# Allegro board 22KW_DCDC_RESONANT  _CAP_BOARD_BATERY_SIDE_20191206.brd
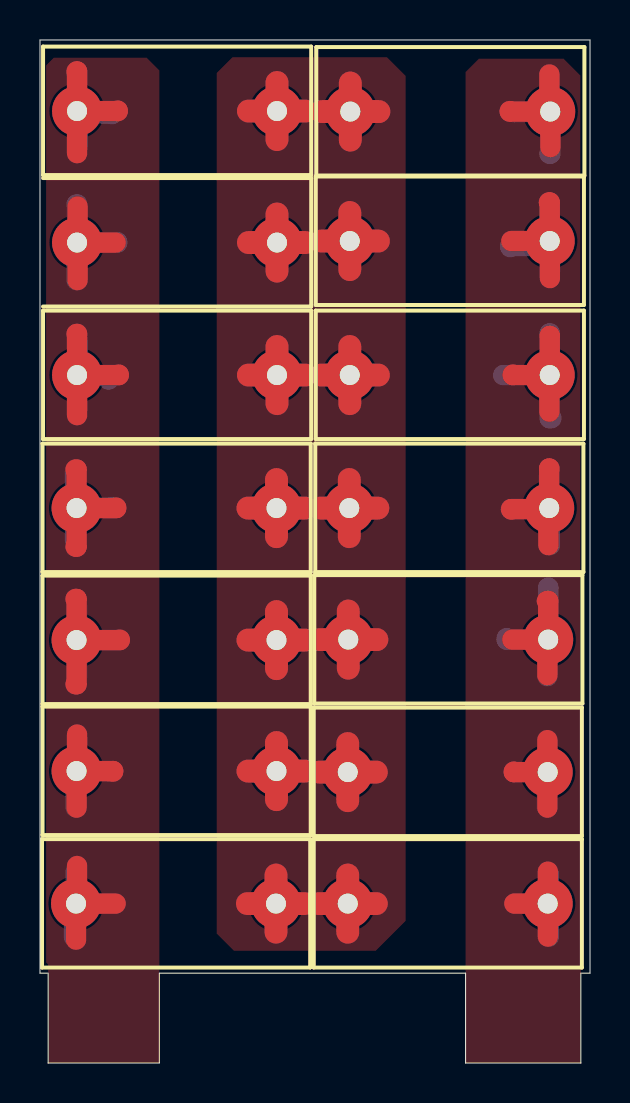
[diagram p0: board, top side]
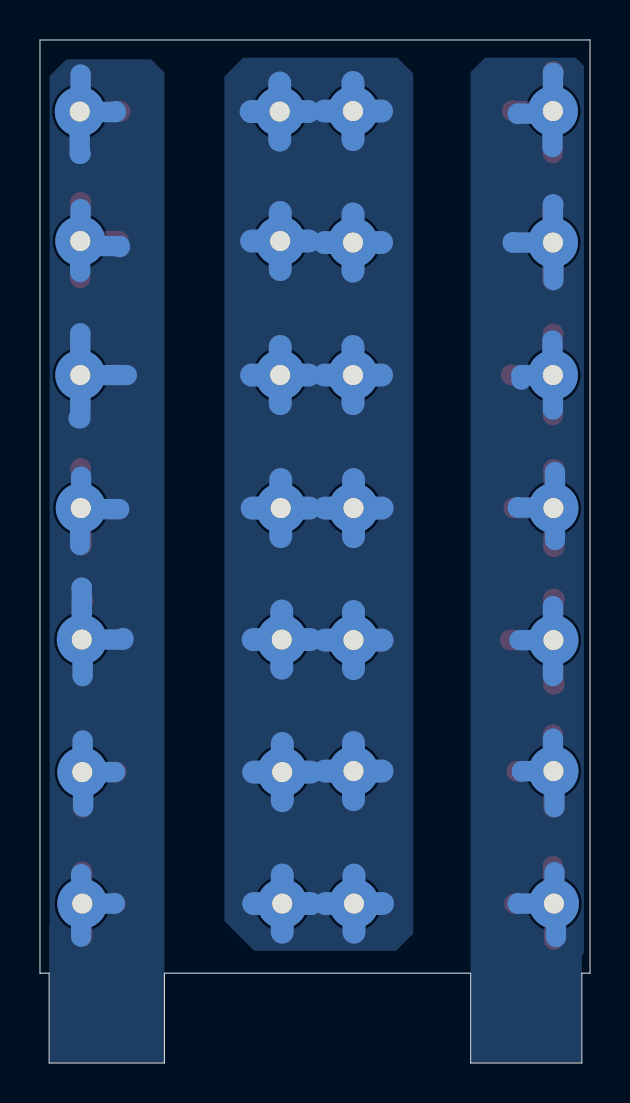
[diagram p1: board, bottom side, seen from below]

Outline 27.51 x 51.18 mm; copper layers: TOP, BOTTOM. Coordinates in mm from the lower left corner of the outline.
Outline path: 0,51.18 27.51,51.18 27.51,4.5 27.05,4.5 27.05,0 21.29,0 21.29,4.5 5.97,4.5 5.97,0 0.41,0 0.41,4.5 0,4.5 0,51.18

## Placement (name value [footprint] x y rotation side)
C1  6.8n  [B32651A7682J000]  1.83 27.76 0 top
C2  6.8n  [B32651A7682J000]  1.8 7.98 0 top
C3  6.8n  [B32651A7682J000]  1.83 14.61 0 top
C4  6.8n  [B32651A7682J000]  1.85 34.42 0 top
C6  6.8n  [B32651A7682J000]  1.85 41.05 0 top
C7  6.8n  [B32651A7682J000]  1.83 21.16 0 top
C9  6.8n  [B32651A7682J000]  1.85 47.62 0 top
C11  6.8n  [B32651A7682J000]  15.47 27.76 0 top
C12  6.8n  [B32651A7682J000]  15.39 7.98 0 top
C13  6.8n  [B32651A7682J000]  15.39 14.55 0 top
C14  6.8n  [B32651A7682J000]  15.49 34.42 0 top
C16  6.8n  [B32651A7682J000]  15.49 41.12 0 top
C17  6.8n  [B32651A7682J000]  15.42 21.18 0 top
C19  6.8n  [B32651A7682J000]  15.52 47.6 0 top

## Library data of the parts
C1-C4 C6 C7 C9 C11-C14 C16 C17 C19 = CAP NP

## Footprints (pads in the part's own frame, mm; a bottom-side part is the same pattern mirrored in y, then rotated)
B32651A7682J000
  round 2.5 hole 1: 1(0,0) 2(10,0)

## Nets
N00441: C1.1 C2.1 C3.1 C4.1 C6.1 C7.1 C9.1
N03629: C1.2 C2.2 C3.2 C4.2 C6.2 C7.2 C9.2 C11.1 C12.1 C13.1 C14.1 C16.1 C17.1 C19.1
N03669: C11.2 C12.2 C13.2 C14.2 C16.2 C17.2 C19.2

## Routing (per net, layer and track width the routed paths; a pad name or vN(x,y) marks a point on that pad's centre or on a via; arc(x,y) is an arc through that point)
N00441: length 78.9
  TOP w1.016: C4.1 1.85,32.41 ; C4.1 1.85,36.47 1.83,36.47 ; C4.1 3.94,34.42 3.94,34.44 ; 1.78,29.69 1.83,29.69 C1.1 ; 1.88,41.05 3.78,41.05 ; 1.88,41.05 1.88,39.17 ; 1.88,41.05 1.88,42.85 ; 1.88,41.05 C6.1 ; 1.78,25.83 1.83,25.83 C1.1 ; C1.1 3.81,27.76 3.81,27.79 ; C9.1 1.85,49.61 1.83,49.61 ; C9.1 3.89,47.62 3.89,47.65 ; C9.1 1.85,45.52 ; 1.85,14.61 C3.1 1.83,12.78 ; 1.85,14.61 3.66,14.61 3.66,14.58 ; 1.85,14.61 1.85,16.43 ; 1.8,6.17 C2.1 1.85,7.98 ; C7.1 3.99,21.16 3.99,21.18 ; C7.1 1.83,23.22 1.78,23.22 ; C7.1 1.83,18.95 1.78,18.95 ; 1.85,9.86 1.85,7.98 ; 1.85,7.98 3.78,7.98
  BOTTOM w1.016: C6.1 1.83,41.05 1.83,39.17 ; C6.1 1.85,42.95 1.83,42.95 ; C6.1 3.86,41.05 3.86,41.07 ; 1.85,32.69 C4.1 1.88,34.42 ; 1.78,7.98 1.7,7.98 1.7,6.3 ; 1.78,7.98 C2.1 3.61,7.98 3.61,8 ; 1.78,7.98 1.78,9.55 ; 1.88,45.82 1.88,47.5 3.61,47.5 3.61,47.47 ; 1.85,16.23 1.85,14.61 ; 1.85,14.61 C3.1 1.78,14.61 1.78,12.8 ; 1.85,14.61 3.4,14.61 3.4,14.58 ; 1.85,21.16 3.53,21.16 ; 1.85,21.16 1.85,22.86 ; 1.85,21.16 1.85,19.35 ; 1.85,21.16 C7.1 ; 3.43,34.19 3.43,34.42 1.88,34.42 ; 1.88,36.14 1.88,34.42 ; 1.75,27.79 1.75,26.16 ; 1.75,27.79 1.75,29.57 ; 1.75,27.79 3.61,27.79 3.61,27.81 ; C9.1 1.85,49.53 1.83,49.53
N03629: length 160.1
  TOP w1.143: C16.1 15.49,42.55 ; C16.1 16.92,41.12 ; C16.1 14.06,41.12 ; C16.1 15.49,39.69 ; 15.47,26.33 C11.1 ; C11.1 14.04,27.76 ; C11.1 16.9,27.76 ; C11.1 15.47,29.19 ; 10.4,27.76 C1.2 ; C1.2 11.83,26.33 ; C1.2 13.26,27.76 ; C1.2 11.83,29.19 ; 11.85,32.99 C4.2 ; C4.2 11.85,35.85 ; C4.2 10.42,34.42 ; C4.2 13.28,34.42 ; 11.85,39.62 C6.2 ; C6.2 11.85,42.48 ; C6.2 10.42,41.05 ; C6.2 13.28,41.05 ; C14.1 15.49,35.85 ; C14.1 16.92,34.42 ; C14.1 14.06,34.42 ; C14.1 15.49,32.99 ; 13.99,21.18 C17.1 ; C17.1 16.85,21.18 ; C17.1 15.42,19.75 ; C17.1 15.42,22.61 ; 15.39,6.55 C12.1 ; C12.1 13.96,7.98 ; C12.1 16.82,7.98 ; C12.1 15.39,9.41 ; 11.85,46.2 C9.2 ; C9.2 11.85,49.05 ; C9.2 13.28,47.62 ; C9.2 10.42,47.62 ; 11.8,6.55 C2.2 ; C2.2 13.23,7.98 ; C2.2 10.37,7.98 ; C2.2 11.8,9.41 ; 10.4,14.61 C3.2 ; C3.2 11.83,13.18 ; C3.2 13.26,14.61 ; C3.2 11.83,16.03 ; 15.39,13.12 C13.1 ; C13.1 13.96,14.55 ; C13.1 16.82,14.55 ; C13.1 15.39,15.98 ; 15.52,46.17 C19.1 ; C19.1 14.09,47.6 ; C19.1 16.95,47.6 ; C19.1 15.52,49.03 ; C7.2 11.83,22.59 ; C7.2 11.83,19.73 ; C7.2 13.26,21.16 ; C7.2 10.4,21.16
  BOTTOM w1.143: C16.1 16.92,41.12 ; C16.1 15.49,39.69 ; C16.1 14.06,41.12 ; C16.1 15.49,42.55 ; C9.2 13.28,47.62 ; C9.2 11.85,46.2 ; C9.2 10.42,47.62 ; C9.2 11.85,49.05 ; 10.4,27.76 C1.2 ; C1.2 13.26,27.76 ; C1.2 11.83,29.19 ; C1.2 11.83,26.33 ; C12.1 15.39,9.41 ; C12.1 16.82,7.98 ; C12.1 15.39,6.55 ; C12.1 13.96,7.98 ; C2.2 11.8,9.41 ; C2.2 13.23,7.98 ; C2.2 11.8,6.55 ; C2.2 10.37,7.98 ; 15.47,26.33 C11.1 ; C11.1 16.9,27.76 ; C11.1 15.47,29.19 ; C11.1 14.04,27.76 ; 13.99,21.18 C17.1 ; C17.1 15.42,22.61 ; C17.1 16.85,21.18 ; C17.1 15.42,19.75 ; C14.1 16.92,34.42 ; C14.1 15.49,35.85 ; C14.1 14.06,34.42 ; C14.1 15.49,32.99 ; C6.2 13.28,41.05 ; C6.2 11.85,42.48 ; C6.2 11.85,39.62 ; C6.2 10.42,41.05 ; C7.2 13.26,21.16 ; C7.2 11.83,19.73 ; C7.2 10.4,21.16 ; C7.2 11.83,22.59 ; 15.39,13.12 C13.1 ; C13.1 13.96,14.55 ; C13.1 15.39,15.98 ; C13.1 16.82,14.55 ; 10.42,34.42 C4.2 ; C4.2 11.85,35.85 ; C4.2 11.85,32.99 ; C4.2 13.28,34.42 ; C19.1 16.95,47.6 ; C19.1 14.09,47.6 ; C19.1 15.52,46.17 ; C19.1 15.52,49.03 ; C3.2 13.26,14.61 ; C3.2 11.83,16.03 ; C3.2 11.83,13.18 ; C3.2 10.4,14.61
N03669: length 78.1
  TOP w1.016: 25.37,21.18 23.62,21.18 ; 25.37,21.18 25.37,19.41 ; 25.37,21.18 C17.2 25.42,23.11 25.35,23.11 ; 25.4,7.98 C12.2 23.72,7.98 ; 25.4,7.98 25.4,6.32 ; 25.4,7.98 25.4,9.58 ; 25.37,14.55 C13.2 ; 25.37,14.55 23.7,14.55 23.7,14.58 ; 25.37,14.55 25.37,12.78 ; 25.37,14.55 25.37,16.15 ; C16.2 23.57,41.12 ; C16.2 25.49,43.05 25.45,43.05 ; C16.2 25.5,41.12 25.5,39.27 ; 25.43,25.91 25.43,27.76 C11.2 25.47,29.74 25.48,29.74 ; 25.44,27.71 23.57,27.71 23.57,27.69 ; 25.48,47.6 C19.2 25.53,47.6 25.53,45.82 ; 25.48,47.6 23.49,47.6 23.49,47.62 ; 25.48,47.6 25.48,49.45 ; 23.65,34.44 23.65,34.42 25.48,34.42 ; 25.5,36.37 25.49,36.37 C14.2 25.48,34.42 ; 25.48,34.42 25.48,32.59
  BOTTOM w1.016: 25.45,7.98 25.45,9.45 ; 25.45,7.98 C12.2 23.77,7.98 23.77,8 ; 25.45,7.98 25.45,6.32 ; 25.5,36.5 25.49,36.5 C14.2 ; 25.48,42.72 25.48,40.87 23.52,40.87 23.52,40.82 ; 25.37,14.55 C13.2 ; 25.37,14.55 25.35,14.55 ; 25.37,14.55 25.37,16.13 ; 25.45,27.71 25.5,27.71 25.5,25.91 ; 25.45,27.71 23.55,27.71 ; 25.45,27.71 25.45,29.34 ; C14.2 25.49,32.26 25.58,32.26 ; C14.2 23.16,34.42 ; 25.35,12.83 25.35,14.55 ; 25.35,14.55 23.75,14.55 ; C16.2 25.5,41.12 25.5,39.57 ; 25.37,21.18 23.34,21.18 23.34,21.26 ; 25.37,21.18 C17.2 25.42,23.77 25.43,23.77 ; 25.37,21.18 25.37,19.35 ; 23.72,47.62 23.72,47.57 25.48,47.57 25.48,49.45 ; C19.2 25.52,45.49 25.48,45.49

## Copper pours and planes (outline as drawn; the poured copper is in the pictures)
N00441 on TOP: 0.3,49.91 0.3,5.03 0.41,4.93 0.41,0 5.97,0 5.97,49.66 5.33,50.29 0.69,50.29
N00441 on BOTTOM: 0.3,49.89 0.3,5.49 0.41,5.38 0.41,0 5.97,0 5.97,49.58 5.26,50.29 0.71,50.29
N03629 on TOP: 18.29,49.38 18.29,7.11 16.79,5.61 9.7,5.61 8.84,6.48 8.84,49.56 8.86,49.56 9.63,50.32 17.35,50.32
N03629 on BOTTOM: 18.29,49.35 18.29,7.11 16.79,5.61 9.7,5.61 8.84,6.48 8.84,49.5 9.63,50.29 17.35,50.29
N03669 on TOP: 27.03,49.4 27.03,6.91 27.05,6.88 27.05,0 21.29,0 21.29,49.58 21.95,50.24 26.19,50.24
N03669 on BOTTOM: 27.03,49.38 27.03,6.91 27.05,6.88 27.05,0 21.29,0 21.29,49.56 21.95,50.22 26.19,50.22

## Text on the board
User.6: FIGURE | SIZE | 39.37 | DRILL CHART: TOP to BOTTOM | ALL UNITS ARE IN MILS | TOLERANCE | +2.99/-2.99 | PLATED | QTY | 28
